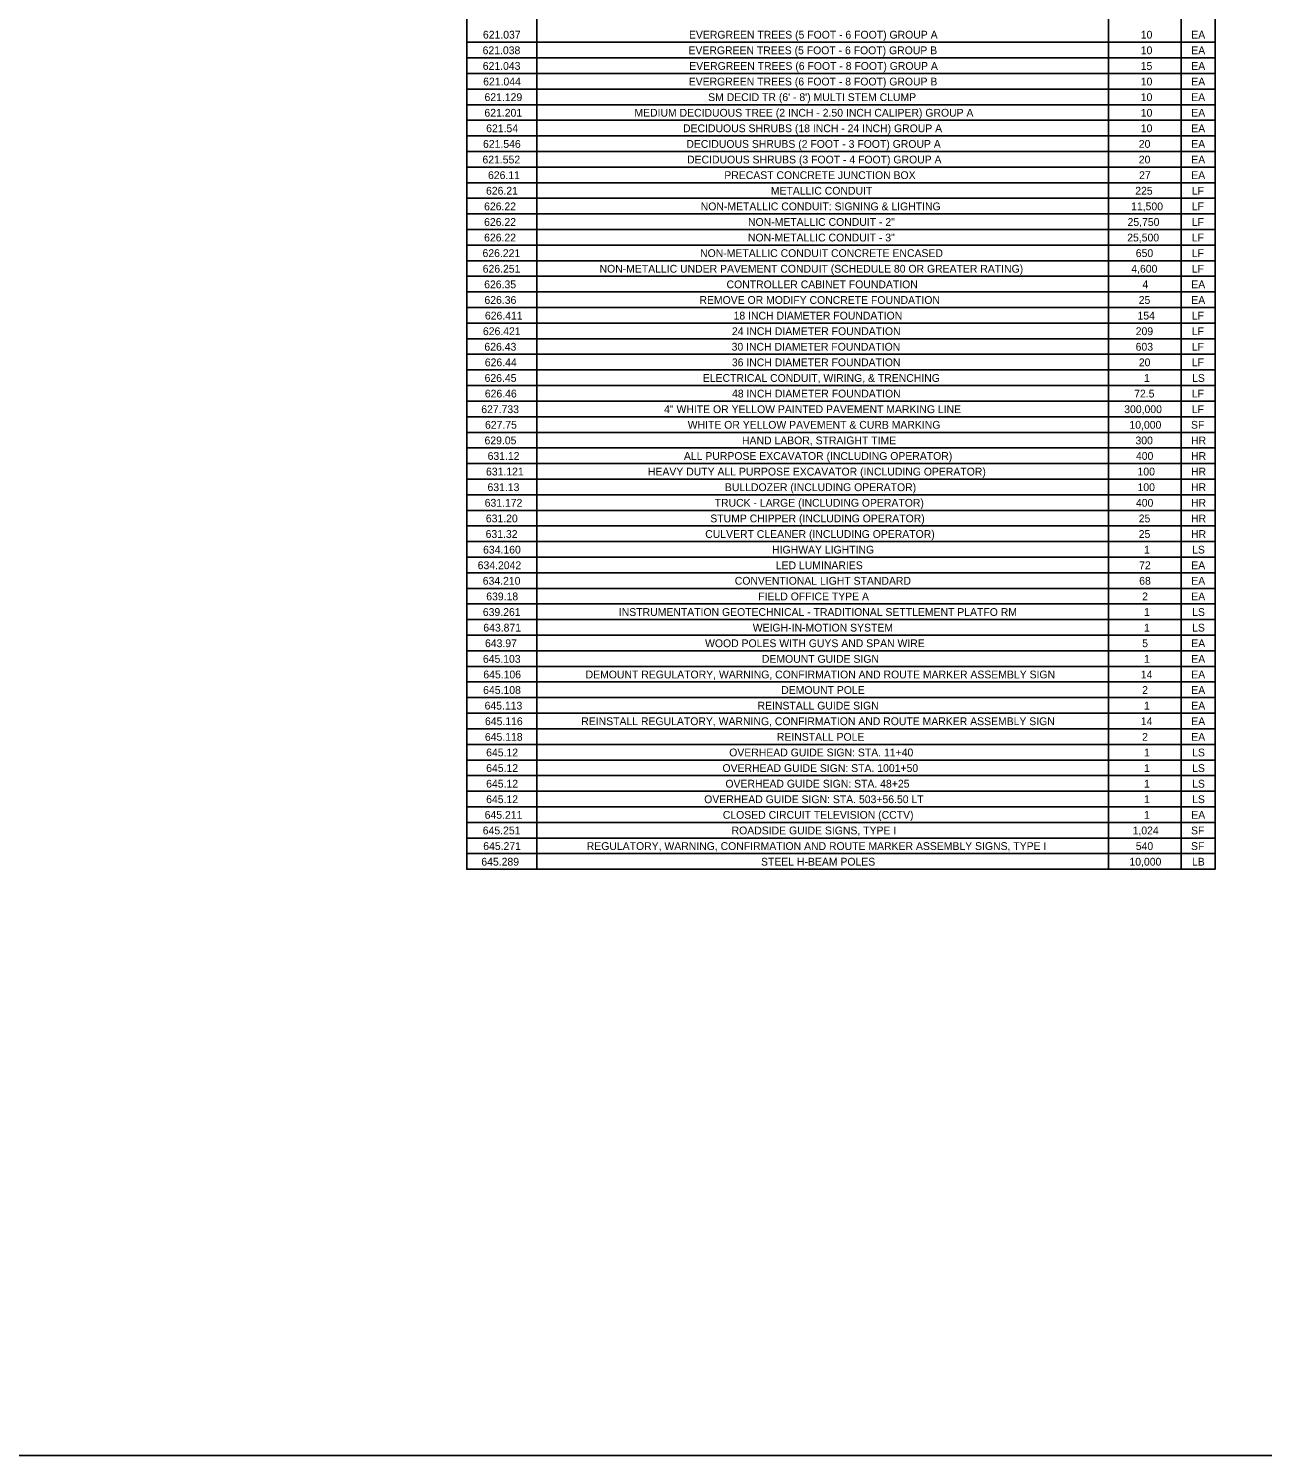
# Model space of a CAD drawing. Extents: x -18.7 to 5.6, y -2.7 to 5.1.
# Drawn here: x -6.783 to -5.226, y 1.503 to 3.303 of the extents above; entities that cross this region are included whole.
import ezdxf

# ---------------------------------------------------------------- set-up
doc = ezdxf.new("R2010")
doc.units = 0
for name, color, linetype in [('ANNOTATION', 7, 'Continuous'), ('BORDER', 7, 'Continuous'), ('Default', 7, 'Continuous')]:
    doc.layers.add(name, color=color, linetype=linetype)

msp = doc.modelspace()

# ---------------------------------------------------------------- linework, layer by layer
at = {"layer": 'BORDER'}
for p, q in [((-6.1418, 3.9551), (-6.1418, 2.2424)), ((-5.4205, 3.9551), (-5.4205, 2.2424)), ((-5.3291, 3.9551), (-5.3291, 2.2424)), ((-6.2304, 3.2858), (-5.2861, 3.2858)), ((-6.2304, 3.2661), (-5.2861, 3.2661)), ((-6.2304, 3.2464), (-5.2861, 3.2464)), ((-6.2304, 3.2267), (-5.2861, 3.2267)), ((-6.2304, 3.207), (-5.2861, 3.207)), ((-6.2304, 3.1873), (-5.2861, 3.1873)), ((-6.2304, 3.1677), (-5.2861, 3.1677)), ((-6.2304, 3.148), (-5.2861, 3.148)), ((-6.2304, 3.1283), (-5.2861, 3.1283)), ((-6.2304, 3.1086), (-5.2861, 3.1086)), ((-6.2304, 3.0889), (-5.2861, 3.0889)), ((-6.2304, 3.0692), (-5.2861, 3.0692)), ((-6.2304, 3.0495), (-5.2861, 3.0495)), ((-6.2304, 3.0299), (-5.2861, 3.0299)), ((-6.2304, 3.0102), (-5.2861, 3.0102)), ((-6.2304, 2.9905), (-5.2861, 2.9905)), ((-6.2304, 2.9708), (-5.2861, 2.9708)), ((-6.2304, 2.9511), (-5.2861, 2.9511)), ((-6.2304, 2.9314), (-5.2861, 2.9314)), ((-6.2304, 2.9117), (-5.2861, 2.9117)), ((-6.2304, 2.8921), (-5.2861, 2.8921)), ((-6.2304, 2.8724), (-5.2861, 2.8724)), ((-6.2304, 2.8527), (-5.2861, 2.8527)), ((-6.2304, 2.833), (-5.2861, 2.833)), ((-6.2304, 2.8133), (-5.2861, 2.8133)), ((-6.2304, 2.7936), (-5.2861, 2.7936)), ((-6.2304, 2.7739), (-5.2861, 2.7739)), ((-6.2304, 2.7543), (-5.2861, 2.7543)), ((-6.2304, 2.7346), (-5.2861, 2.7346)), ((-6.2304, 2.7149), (-5.2861, 2.7149)), ((-6.2304, 2.6952), (-5.2861, 2.6952)), ((-6.2304, 2.6755), (-5.2861, 2.6755)), ((-6.2304, 2.6558), (-5.2861, 2.6558)), ((-6.2304, 2.6361), (-5.2861, 2.6361)), ((-6.2304, 2.6165), (-5.2861, 2.6165)), ((-6.2304, 2.5968), (-5.2861, 2.5968)), ((-6.2304, 2.5771), (-5.2861, 2.5771)), ((-6.2304, 2.5574), (-5.2861, 2.5574)), ((-6.2304, 2.5377), (-5.2861, 2.5377)), ((-6.2304, 2.518), (-5.2861, 2.518)), ((-6.2304, 2.4983), (-5.2861, 2.4983)), ((-6.2304, 2.4787), (-5.2861, 2.4787)), ((-6.2304, 2.459), (-5.2861, 2.459)), ((-6.2304, 2.4393), (-5.2861, 2.4393)), ((-6.2304, 2.4196), (-5.2861, 2.4196)), ((-6.2304, 2.3999), (-5.2861, 2.3999)), ((-6.2304, 2.3802), (-5.2861, 2.3802)), ((-6.2304, 2.3605), (-5.2861, 2.3605)), ((-6.2304, 2.3408), (-5.2861, 2.3408)), ((-6.2304, 2.3212), (-5.2861, 2.3212)), ((-6.2304, 2.3015), (-5.2861, 2.3015)), ((-6.2304, 2.2818), (-5.2861, 2.2818)), ((-6.2304, 2.2621), (-5.2861, 2.2621)), ((-6.2304, 2.2424), (-5.2861, 2.2424))]:
    msp.add_line(p, q, dxfattribs=at)
msp.add_lwpolyline([(-6.2304, 3.9748), (-5.2861, 3.9748), (-5.2861, 2.2424), (-6.2304, 2.2424)], close=True, dxfattribs=at)
at = {"layer": 'Default'}
msp.add_lwpolyline([(-10.8151, 5.0978), (-2.7516, 5.0978), (-2.7516, 1.5028), (-10.8151, 1.5028)], close=True, dxfattribs=at)

# ---------------------------------------------------------------- texts
at = {"layer": 'ANNOTATION'}
for s, height, p in [('621.037', 0.00984, (-6.21, 3.2904)), ('EVERGREEN TREES (5 FOOT - 6 FOOT) GROUP A', 0.009843, (-5.95, 3.2904)), ('10', 0.00984, (-5.3799, 3.2904)), ('EA', 0.00984, (-5.3162, 3.2904)), ('621.038', 0.00984, (-6.2104, 3.2707)), ('EVERGREEN TREES (5 FOOT - 6 FOOT) GROUP B', 0.009843, (-5.9506, 3.2707)), ('10', 0.00984, (-5.3799, 3.2707)), ('EA', 0.00984, (-5.3162, 3.2707)), ('621.043', 0.00984, (-6.2102, 3.251)), ('EVERGREEN TREES (6 FOOT - 8 FOOT) GROUP A', 0.009843, (-5.9497, 3.251)), ('15', 0.00984, (-5.38, 3.251)), ('EA', 0.00984, (-5.3162, 3.251)), ('621.044', 0.00984, (-6.2097, 3.2313)), ('EVERGREEN TREES (6 FOOT - 8 FOOT) GROUP B', 0.009843, (-5.9503, 3.2313)), ('10', 0.00984, (-5.3799, 3.2313)), ('EA', 0.00984, (-5.3162, 3.2313)), ('621.129', 0.00984, (-6.208, 3.2116)), ("SM DECID TR (6' - 8') MULTI STEM CLUMP", 0.009843, (-5.9258, 3.2116)), ('10', 0.00984, (-5.3799, 3.2116)), ('EA', 0.00984, (-5.3162, 3.2116)), ('621.201', 0.00984, (-6.2081, 3.1919)), ('MEDIUM DECIDUOUS TREE (2 INCH - 2.50 INCH CALIPER) GROUP A', 0.009843, (-6.0189, 3.1919)), ('10', 0.00984, (-5.3799, 3.1919)), ('EA', 0.00984, (-5.3162, 3.1919)), ('621.54', 0.00984, (-6.2059, 3.1723)), ('DECIDUOUS SHRUBS (18 INCH - 24 INCH) GROUP A', 0.009843, (-5.9575, 3.1723)), ('10', 0.00984, (-5.3799, 3.1723)), ('EA', 0.00984, (-5.3162, 3.1723)), ('621.546', 0.00984, (-6.2099, 3.1526)), ('DECIDUOUS SHRUBS (2 FOOT - 3 FOOT) GROUP A', 0.009843, (-5.9533, 3.1526)), ('20', 0.00984, (-5.3824, 3.1526)), ('EA', 0.00984, (-5.3162, 3.1526)), ('621.552', 0.00984, (-6.2106, 3.1329)), ('DECIDUOUS SHRUBS (3 FOOT - 4 FOOT) GROUP A', 0.009843, (-5.9524, 3.1329)), ('20', 0.00984, (-5.3824, 3.1329)), ('EA', 0.00984, (-5.3162, 3.1329)), ('626.11', 0.00984, (-6.2036, 3.1132)), ('PRECAST CONCRETE JUNCTION BOX', 0.009843, (-5.9054, 3.1132)), ('27', 0.00984, (-5.382, 3.1132)), ('EA', 0.00984, (-5.3162, 3.1132)), ('626.21', 0.00984, (-6.2061, 3.0935)), ('METALLIC CONDUIT', 0.009843, (-5.8467, 3.0935)), ('225', 0.00984, (-5.3869, 3.0935)), ('LF', 0.00984, (-5.3155, 3.0935)), ('626.22', 0.00984, (-6.2085, 3.0738)), ('NON-METALLIC CONDUIT: SIGNING & LIGHTING', 0.009843, (-5.9352, 3.0738)), ('11,500', 0.00984, (-5.3921, 3.0738)), ('LF', 0.00984, (-5.3155, 3.0738)), ('626.22', 0.00984, (-6.2085, 3.0541)), ('NON-METALLIC CONDUIT - 2"', 0.009843, (-5.8755, 3.0541)), ('25,750', 0.00984, (-5.3966, 3.0541)), ('LF', 0.00984, (-5.3155, 3.0541)), ('626.22', 0.00984, (-6.2085, 3.0345)), ('NON-METALLIC CONDUIT - 3"', 0.009843, (-5.8756, 3.0345)), ('25,500', 0.00984, (-5.397, 3.0345)), ('LF', 0.00984, (-5.3155, 3.0345)), ('626.221', 0.00984, (-6.2105, 3.0148)), ('NON-METALLIC CONDUIT CONCRETE ENCASED', 0.009843, (-5.936, 3.0148)), ('650', 0.00984, (-5.3862, 3.0148)), ('LF', 0.00984, (-5.3155, 3.0148)), ('626.251', 0.00984, (-6.2103, 2.9951)), ('NON-METALLIC UNDER PAVEMENT CONDUIT (SCHEDULE 80 OR GREATER RATING)', 0.009843, (-6.0629, 2.9951)), ('4,600', 0.00984, (-5.3919, 2.9951)), ('LF', 0.00984, (-5.3155, 2.9951)), ('626.35', 0.00984, (-6.2084, 2.9754)), ('CONTROLLER CABINET FOUNDATION', 0.009843, (-5.9026, 2.9754)), ('4', 0.00984, (-5.3778, 2.9754)), ('EA', 0.00984, (-5.3162, 2.9754)), ('626.36', 0.00984, (-6.2081, 2.9557)), ('REMOVE OR MODIFY CONCRETE FOUNDATION', 0.009843, (-5.9368, 2.9557)), ('25', 0.00984, (-5.3825, 2.9557)), ('EA', 0.00984, (-5.3162, 2.9557)), ('626.411', 0.00984, (-6.2075, 2.936)), ('18 INCH DIAMETER FOUNDATION', 0.009843, (-5.8937, 2.936)), ('154', 0.00984, (-5.384, 2.936)), ('LF', 0.00984, (-5.3155, 2.936)), ('626.421', 0.00984, (-6.21, 2.9163)), ('24 INCH DIAMETER FOUNDATION', 0.009843, (-5.8958, 2.9163)), ('209', 0.00984, (-5.3863, 2.9163)), ('LF', 0.00984, (-5.3155, 2.9163)), ('626.43', 0.00984, (-6.2081, 2.8967)), ('30 INCH DIAMETER FOUNDATION', 0.009843, (-5.8962, 2.8967)), ('603', 0.00984, (-5.3864, 2.8967)), ('LF', 0.00984, (-5.3155, 2.8967)), ('626.44', 0.00984, (-6.2076, 2.877)), ('36 INCH DIAMETER FOUNDATION', 0.009843, (-5.8959, 2.877)), ('20', 0.00984, (-5.3824, 2.877)), ('LF', 0.00984, (-5.3155, 2.877)), ('626.45', 0.00984, (-6.2079, 2.8573)), ('ELECTRICAL CONDUIT, WIRING, & TRENCHING', 0.009843, (-5.9325, 2.8573)), ('1', 0.00984, (-5.3758, 2.8573)), ('LS', 0.00984, (-5.3151, 2.8573)), ('626.46', 0.00984, (-6.2076, 2.8376)), ('48 INCH DIAMETER FOUNDATION', 0.009843, (-5.8957, 2.8376)), ('72.5', 0.00984, (-5.3882, 2.8376)), ('LF', 0.00984, (-5.3155, 2.8376)), ('627.733', 0.00984, (-6.2121, 2.8179)), ('4" WHITE OR YELLOW PAINTED PAVEMENT MARKING LINE', 0.009843, (-5.9814, 2.8179)), ('300,000', 0.00984, (-5.4008, 2.8179)), ('LF', 0.00984, (-5.3155, 2.8179)), ('627.75', 0.00984, (-6.2074, 2.7982)), ('WHITE OR YELLOW PAVEMENT & CURB MARKING', 0.009843, (-5.9516, 2.7982)), ('10,000', 0.00984, (-5.3942, 2.7982)), ('SF', 0.00984, (-5.3165, 2.7982)), ('629.05', 0.00984, (-6.208, 2.7785)), ('HAND LABOR, STRAIGHT TIME', 0.009843, (-5.8831, 2.7785)), ('300', 0.00984, (-5.3866, 2.7785)), ('HR', 0.00984, (-5.3165, 2.7785)), ('631.12', 0.00984, (-6.2041, 2.7589)), ('ALL PURPOSE EXCAVATOR (INCLUDING OPERATOR)', 0.009843, (-5.9564, 2.7589)), ('400', 0.00984, (-5.386, 2.7589)), ('HR', 0.00984, (-5.3165, 2.7589)), ('631.121', 0.00984, (-6.2061, 2.7392)), ('HEAVY DUTY ALL PURPOSE EXCAVATOR (INCLUDING OPERATOR)', 0.009843, (-6.0018, 2.7392)), ('100', 0.00984, (-5.384, 2.7392)), ('HR', 0.00984, (-5.3165, 2.7392)), ('631.13', 0.00984, (-6.2042, 2.7195)), ('BULLDOZER (INCLUDING OPERATOR)', 0.009843, (-5.9047, 2.7195)), ('100', 0.00984, (-5.384, 2.7195)), ('HR', 0.00984, (-5.3165, 2.7195)), ('631.172', 0.00984, (-6.2078, 2.6998)), ('TRUCK - LARGE (INCLUDING OPERATOR)', 0.009843, (-5.9176, 2.6998)), ('400', 0.00984, (-5.386, 2.6998)), ('HR', 0.00984, (-5.3165, 2.6998)), ('631.20', 0.00984, (-6.2063, 2.6801)), ('STUMP CHIPPER (INCLUDING OPERATOR)', 0.009843, (-5.9231, 2.6801)), ('25', 0.00984, (-5.3825, 2.6801)), ('HR', 0.00984, (-5.3165, 2.6801)), ('631.32', 0.00984, (-6.2066, 2.6604)), ('CULVERT CLEANER (INCLUDING OPERATOR)', 0.009843, (-5.9295, 2.6604)), ('25', 0.00984, (-5.3825, 2.6604)), ('HR', 0.00984, (-5.3165, 2.6604)), ('634.160', 0.00984, (-6.2098, 2.6407)), ('HIGHWAY LIGHTING', 0.009843, (-5.8451, 2.6407)), ('1', 0.00984, (-5.3758, 2.6407)), ('LS', 0.00984, (-5.3151, 2.6407)), ('634.2042', 0.00984, (-6.2166, 2.621)), ('LED LUMINARIES', 0.009843, (-5.8405, 2.621)), ('72', 0.00984, (-5.382, 2.621)), ('EA', 0.00984, (-5.3162, 2.621)), ('634.210', 0.00984, (-6.2102, 2.6014)), ('CONVENTIONAL LIGHT STANDARD', 0.009843, (-5.8922, 2.6014)), ('68', 0.00984, (-5.3819, 2.6014)), ('EA', 0.00984, (-5.3162, 2.6014)), ('639.18', 0.00984, (-6.2058, 2.5817)), ('FIELD OFFICE TYPE A', 0.009843, (-5.8626, 2.5817)), ('2', 0.00984, (-5.3782, 2.5817)), ('EA', 0.00984, (-5.3162, 2.5817)), ('639.261', 0.00984, (-6.2101, 2.562)), ('INSTRUMENTATION GEOTECHNICAL - TRADITIONAL SETTLEMENT PLATFO RM', 0.009843, (-6.0385, 2.562)), ('1', 0.00984, (-5.3758, 2.562)), ('LS', 0.00984, (-5.3151, 2.562)), ('643.871', 0.00984, (-6.2095, 2.5423)), ('WEIGH-IN-MOTION SYSTEM', 0.009843, (-5.8695, 2.5423)), ('1', 0.00984, (-5.3758, 2.5423)), ('LS', 0.00984, (-5.3151, 2.5423)), ('643.97', 0.00984, (-6.2074, 2.5226)), ('WOOD POLES WITH GUYS AND SPAN WIRE', 0.009843, (-5.9297, 2.5226)), ('5', 0.00984, (-5.3781, 2.5226)), ('EA', 0.00984, (-5.3162, 2.5226)), ('645.103', 0.00984, (-6.21, 2.5029)), ('DEMOUNT GUIDE SIGN', 0.009843, (-5.858, 2.5029)), ('1', 0.00984, (-5.3758, 2.5029)), ('EA', 0.00984, (-5.3162, 2.5029)), ('645.106', 0.00984, (-6.2095, 2.4832)), ('DEMOUNT REGULATORY, WARNING, CONFIRMATION AND ROUTE MARKER ASSEMBLY SIGN', 0.009843, (-6.0804, 2.4832)), ('14', 0.00984, (-5.3798, 2.4832)), ('EA', 0.00984, (-5.3162, 2.4832)), ('645.108', 0.00984, (-6.2097, 2.4636)), ('DEMOUNT POLE', 0.009843, (-5.8336, 2.4636)), ('2', 0.00984, (-5.3782, 2.4636)), ('EA', 0.00984, (-5.3162, 2.4636)), ('645.113', 0.00984, (-6.2079, 2.4439)), ('REINSTALL GUIDE SIGN', 0.009843, (-5.8635, 2.4439)), ('1', 0.00984, (-5.3758, 2.4439)), ('EA', 0.00984, (-5.3162, 2.4439)), ('645.116', 0.00984, (-6.2074, 2.4242)), ('REINSTALL REGULATORY, WARNING, CONFIRMATION AND ROUTE MARKER ASSEMBLY SIGN', 0.009843, (-6.0859, 2.4242)), ('14', 0.00984, (-5.3798, 2.4242)), ('EA', 0.00984, (-5.3162, 2.4242)), ('645.118', 0.00984, (-6.2075, 2.4045)), ('REINSTALL POLE', 0.009843, (-5.8391, 2.4045)), ('2', 0.00984, (-5.3782, 2.4045)), ('EA', 0.00984, (-5.3162, 2.4045)), ('645.12', 0.00984, (-6.2059, 2.3848)), ('OVERHEAD GUIDE SIGN: STA. 11+40', 0.009843, (-5.8992, 2.3848)), ('1', 0.00984, (-5.3758, 2.3848)), ('LS', 0.00984, (-5.3151, 2.3848)), ('645.12', 0.00984, (-6.2059, 2.3651)), ('OVERHEAD GUIDE SIGN: STA. 1001+50', 0.009843, (-5.9077, 2.3651)), ('1', 0.00984, (-5.3758, 2.3651)), ('LS', 0.00984, (-5.3151, 2.3651)), ('645.12', 0.00984, (-6.2059, 2.3454)), ('OVERHEAD GUIDE SIGN: STA. 48+25', 0.009843, (-5.904, 2.3454)), ('1', 0.00984, (-5.3758, 2.3454)), ('LS', 0.00984, (-5.3151, 2.3454)), ('645.12', 0.00984, (-6.2059, 2.3258)), ('OVERHEAD GUIDE SIGN: STA. 503+56.50 LT', 0.009843, (-5.9308, 2.3258)), ('1', 0.00984, (-5.3758, 2.3258)), ('LS', 0.00984, (-5.3151, 2.3258)), ('645.211', 0.00984, (-6.2078, 2.3061)), ('CLOSED CIRCUIT TELEVISION (CCTV)', 0.009843, (-5.9073, 2.3061)), ('1', 0.00984, (-5.3758, 2.3061)), ('EA', 0.00984, (-5.3162, 2.3061)), ('645.251', 0.00984, (-6.2102, 2.2864)), ('ROADSIDE GUIDE SIGNS, TYPE I', 0.009843, (-5.8962, 2.2864)), ('1,024', 0.00984, (-5.3902, 2.2864)), ('SF', 0.00984, (-5.3165, 2.2864)), ('645.271', 0.00984, (-6.2096, 2.2667)), ('REGULATORY, WARNING, CONFIRMATION AND ROUTE MARKER ASSEMBLY SIGNS, TYPE I', 0.009843, (-6.079, 2.2667)), ('540', 0.00984, (-5.3862, 2.2667)), ('SF', 0.00984, (-5.3165, 2.2667)), ('645.289', 0.00984, (-6.212, 2.247)), ('STEEL H-BEAM POLES', 0.009843, (-5.8591, 2.247)), ('10,000', 0.00984, (-5.3942, 2.247)), ('LB', 0.00984, (-5.3153, 2.247))]:
    msp.add_text(s, height=height, dxfattribs=at).set_placement(p)

doc.saveas('drawing.dxf')
